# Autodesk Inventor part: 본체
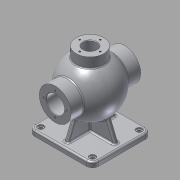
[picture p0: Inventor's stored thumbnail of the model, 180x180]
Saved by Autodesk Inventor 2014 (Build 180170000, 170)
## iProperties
Created: 2015-10
Part Number: 본체
Material: Aluminum 6061
Document SubType Name: Modeling
Designer: youjin09
Density: 2.71 g/cm^3
Appearance: Aluminum - Flat
Mass: 1506.87 g
Surface Area: 1176.12 cm^2
Volume: 556.041 cm^3
Author: youjin09
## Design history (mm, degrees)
sketch "Sketch1"
  geometry: L1 (-62.5, 57.5)-(62.5, 57.5); L2 (62.5, 57.5)-(62.5, -57.5); L3 (62.5, -57.5)-(-62.5, -57.5); L4 (-62.5, -57.5)-(-62.5, 57.5); L5 (-62.5, 57.5)-(62.5, -57.5); L6 (62.5, 57.5)-(-62.5, -57.5); 1 further point
  constraints: 12 end point, 2 midpoint, 2 parallel, 1 horizontal, 1 perpendicular
  dimensions: "d0" = 125 distance of L2.end L3.end; "d1" = 115 distance of L1.end L2.end
extrude "Extrusion1" new body sketch "Sketch1" distance "d2" = 10; taper "d3" = 0 deg
fillet "Fillet1" dims "d4" = 12
sketch "Sketch2"
  geometry: C1 r 6 at (-50.5, 45.5); C2 r 6 at (50.5, 45.5); C3 r 6 at (-50.5, -45.5); C4 r 6 at (50.5, -45.5); A1 r 12 centre (-50.5, 45.5) between (-50.5, 57.5) and (-62.5, 45.5) reference; A2 r 12 centre (-50.5, -45.5) between (-62.5, -45.5) and (-50.5, -57.5) reference; A3 r 12 centre (50.5, -45.5) between (50.5, -57.5) and (62.5, -45.5) reference; A4 r 12 centre (50.5, 45.5) between (62.5, 45.5) and (50.5, 57.5) reference; 1 further point
  constraints: 4 centre point, 4 coincident
  dimensions: "d6" = 12 diameter of C1; "d7" = 12 diameter of C2; "d8" = 12 diameter of C3; "d9" = 12 diameter of C4
extrude "Extrusion2" cut sketch "Sketch2" distance "d10" = 3; taper "d11" = 0 deg
sketch "Sketch3"
  geometry: C1 r 6 at (0, 0) reference; C2 r 6 at (0, 91) reference; C3 r 6 at (101, 91) reference; C4 r 6 at (101, 0) reference; C5 r 4 at (0, 0); C6 r 4 at (0, 91); C7 r 4 at (101, 91); C8 r 4 at (101, 0); 1 further point
  constraints: 4 centre point, 4 coincident
  dimensions: "d12" = 8 diameter of C5; "d13" = 8 diameter of C6; "d14" = 8 diameter of C7; "d15" = 8 diameter of C8
extrude "Extrusion3" cut sketch "Sketch3" stored distance "d16" = 3; taper "d17" = 0 deg
sketch "Sketch4"
  geometry: L1 (45.5, 0)-(-45.5, 0) reference; L2 (-53, 85)-(53, 85); A1 r 53 centre (0, 85) between (53, 85) and (-53, 85); 2 further points
  constraints: 2 end point, 2 point on circle, 1 centre point, 1 midpoint, 1 parallel, 1 vertical alignment
  dimensions: "d18" = 53 radius of A1; "d19" = 85 distance from line of L1 A1.centre; "d20" = 106 distance of L2.start L2.end
revolve "Revolution1" sketch "Sketch4" stored, may be unused: angle "d21" = 90 deg
workplane "Work Plane1"
sketch "Sketch5"
  geometry: C1 r 27 at (0, 0); 1 further point
  constraints: 1 centre point, 1 coincident
  dimensions: "d23" = 54 diameter of C1
extrude "Extrusion4" join sketch "Sketch5" stored distance "d24" = 3; taper "d25" = 0 deg
sketch "Sketch8"
  geometry: L1 (-57.5, 10)-(-57.5, 0) reference; L2 (-57.5, 10)-(-45.5, 10) reference; L3 (-45.5, 10)-(45.5, 10) reference; L4 (39.5, 10)-(51.5, 10) reference; L5 (45.5, 10)-(57.5, 10) reference; L6 (57.5, 10)-(57.5, 0) reference; L7 (33.719, 44.109)-(47.5, 10); L8 (-33.719, 44.109)-(-47.5, 10); A1 r 53 centre (0, 85) between (-27, 130.607) and (27, 130.607) reference; 1 further point
  constraints: 4 end point, 2 point on circle, 2 point on line
  dimensions: "d32" = 10 distance from line of L7.end L6; "d33" = 22 deg angle of L7 L6; "d34" = 10 distance from line of L8.end L1; "d35" = 22 deg angle of L8 L1
sketch "Sketch9"
  geometry: L1 (43, 85)-(-43, 85); A1 r 43 centre (0, 85) between (43, 85) and (-43, 85); 1 further point
  constraints: 2 end point, 2 point on circle, 1 centre point, 1 horizontal, 1 vertical alignment
  dimensions: "d38" = 43 radius of A1; "d39" = 85 distance of A1.centre point (0, 0); "d40" = 86 distance of L1.start L1.end
revolve "Revolution2" sketch "Sketch9" stored, may be unused: angle "d41" = 90 deg
workplane "Work Plane2"
sketch "Sketch11"
  geometry: C1 r 31 at (0, 85); 1 further point
  constraints: 1 centre point, 1 vertical alignment
  dimensions: "d45" = 62 diameter of C1; "d46" = 85 distance of point (0, 0) C1.centre
extrude "Extrusion7" join sketch "Sketch11" stored distance "d47" = 8; taper "d48" = 0 deg
mirror "Mirror1"
sketch "Sketch12"
  geometry: C1 r 31 at (0, 0) reference; C2 r 17.5 at (0, 0); 1 further point
  constraints: 1 centre point, 1 coincident
  dimensions: "d49" = 35 diameter of C2
extrude "Extrusion8" cut sketch "Sketch12" distance "d50" = 16; taper "d51" = 0 deg
sketch "Sketch13"
  geometry: C1 r 17.5 at (0, 0) reference; C2 r 18.5 at (0, 0); 1 further point
  constraints: 1 centre point, 1 coincident
  dimensions: "d52" = 37 diameter of C2
extrude "Extrusion9" cut sketch "Sketch13" distance "d53" = 1.75; taper "d54" = 0 deg
sketch "Sketch14"
  geometry: C1 r 18.5 at (0, 0) reference; C2 r 17.5 at (0, 0); 1 further point
  constraints: 1 centre point, 1 coincident
  dimensions: "d55" = 35 diameter of C2
extrude "Extrusion10" cut sketch "Sketch14" distance "d56" = 30; taper "d57" = 0 deg
sketch "Sketch15"
  geometry: C1 r 31 at (0, 0) reference; C2 r 17.5 at (0, 0); 1 further point
  constraints: 1 centre point, 1 coincident
  dimensions: "d58" = 35 diameter of C2
extrude "Extrusion11" cut sketch "Sketch15" distance "d59" = 50; taper "d60" = 0 deg
sketch "Sketch16"
  geometry: C1 r 17.5 at (0, 0) reference; C2 r 31 at (0, 0) reference; A1 r 22.5 centre (0, 0) between (-22.5, 0) and (0, 22.5); 3 further points
  constraints: 4 point on circle, 2 horizontal alignment, 2 vertical alignment, 1 centre point, 1 coincident
  dimensions: "d61" = 45 diameter of A1
hole "Hole1" sketch "Sketch16" at (0, 22.5), (0, -22.5), (-22.5, 0), (22.5, 0) diameter "d62" = 3.242; stored, may be unused: countersink angle "d66" = 90 deg, drill point angle "d68" = 118 deg; dims "d63" = 12, "d64" = 4, "d65" = 2, "d67" = 15
sketch "Sketch17"
  geometry: C1 r 17.5 at (0, 0) reference; C2 r 31 at (0, 0) reference; A1 r 24 centre (0, 0) between (0, 24) and (-24, 0); 3 further points
  constraints: 4 point on circle, 2 horizontal alignment, 2 vertical alignment, 1 centre point, 1 coincident
  dimensions: "d69" = 48 diameter of A1
hole "Hole2" sketch "Sketch17" at (0, 24), (0, -24), (-24, 0), (24, 0) diameter "d70" = 3.242; stored, may be unused: countersink angle "d74" = 90 deg, drill point angle "d76" = 118 deg; dims "d71" = 16, "d72" = 4, "d73" = 2, "d75" = 19
sketch "Sketch18"
  geometry: C1 r 27 at (0, 0) reference; C2 r 13 at (0, 0)
  constraints: 1 centre point, 1 coincident
  dimensions: "d77" = 26 diameter of C2
extrude "Extrusion12" cut sketch "Sketch18" distance "d78" = 50; taper "d79" = 0 deg
sketch "Sketch19"
  geometry: C1 r 13 at (0, 0) reference; C2 r 27 at (0, 0) reference; A1 r 20 centre (0, 0) between (0, 20) and (20, 0); 2 further points
  constraints: 4 point on circle, 2 horizontal alignment, 2 vertical alignment, 1 centre point, 1 coincident
  dimensions: "d80" = 40 diameter of A1
hole "Hole3" sketch "Sketch19" at (0, 20), (0, -20), (-20, 0), (20, 0) diameter "d81" = 3.242; stored, may be unused: countersink angle "d85" = 90 deg, drill point angle "d87" = 118 deg; dims "d82" = 9, "d83" = 4, "d84" = 2, "d86" = 11
workplane "Work Plane3"
sketch "Sketch21"
  geometry: L1 (45.5, 0)-(-45.5, 0) reference; L2 (-27, 150)-(27, 150) reference; L3 (-27, 130.607)-(27, 130.607) reference; L4 (-27, 150)-(27, 150) reference; 3 further points
  constraints: 1 midpoint, 1 vertical alignment, 1 other
  dimensions: "d89" = 10 distance from line of point (0, 140) L2; "d97" = 27 horizontal distance of point (0, 140) L2.start (derived)
emboss "Emboss1" sketch "Sketch21" dims "d90" = 0.5, "d91" = 0
chamfer "Chamfer1" distance "d92" = 1; stored, may be unused: second distance "d93" = 2, angle "d94" = 45 deg
fillet "Fillet2" dims "d95" = 3
sketch "Sketch22"
  geometry: L1 (-4, 4)-(4, 4); L2 (4, 4)-(4, -4); L3 (4, -4)-(-4, -4); L4 (-4, -4)-(-4, 4); L5 (-4, 4)-(4, -4); L6 (4, 4)-(-4, -4); 1 further point
  constraints: 12 end point, 2 midpoint, 2 parallel, 1 horizontal, 1 perpendicular
  dimensions: "d98" = 8 distance of L2.end L3.end; "d99" = 8 distance of L1.end L2.end
extrude "Extrusion13" join sketch "Sketch22" stored distance "d100" = 10; taper "d101" = 0 deg
feature "Rib1" dims "d102" = 1, "d103" = 8, "d104" = 0, "d105" = 0, "d106" = 1, "d107" = 1
feature "Rib2" dims "d108" = 1, "d109" = 8, "d110" = 0, "d111" = 0, "d112" = 1, "d113" = 1
sketch "Sketch23"
  geometry: L1 (-62.5, 0)-(-62.5, 7) reference; L2 (-59.5, 10)-(-50.5, 10) reference; L3 (-56.5, 10)-(-44.5, 10) reference; L4 (-50.5, 10)-(50.5, 10) reference; L5 (44.5, 10)-(56.5, 10) reference; L6 (50.5, 10)-(59.5, 10) reference; L7 (62.5, 7)-(50.5, 7) reference; L8 (62.5, 7)-(62.5, 0) reference; L9 (62.5, 0)-(50.5, 0) reference; L10 (50.5, 0)-(50.5, 7) reference; L11 (-37.379, 47.426)-(-52.5, 10); L12 (37.379, 47.426)-(52.5, 10); A1 r 53 centre (0, 85) between (-28.393, 129.753) and (28.393, 129.753) reference; 1 further point
  constraints: 4 end point, 2 point on circle, 2 point on line
  dimensions: "d114" = 10 distance from line of L11.end L1; "d115" = 22 deg angle of L1 L11; "d116" = 10 distance from line of L12.end L8; "d117" = 22 deg angle of L12 L8
  node "Projected Loop4"
feature "Rib3" dims "d118" = 1, "d119" = 8, "d120" = 0, "d121" = 0, "d122" = 1, "d123" = 1
feature "Rib4" dims "d124" = 1, "d125" = 8, "d126" = 0, "d127" = 0, "d128" = 1, "d129" = 1
fillet "Fillet4" dims "d130" = 3
body "Solid1"
node "Projected Loop1"
node "Projected Loop2"
node "Projected Loop3"
other parameters: "d44" = 68, "d88" = -27.5
